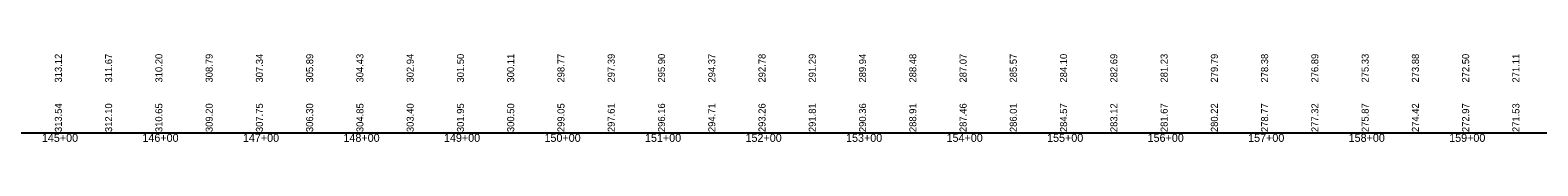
# Model space of a CAD drawing. Extents: x 1876258 to 1932803, y 754739 to 837911.
# Drawn here: x 1892831 to 1894330, y 830495 to 830583 of the extents above; entities that cross this region are included whole.
import ezdxf

# ---------------------------------------------------------------- set-up
doc = ezdxf.new("R2010")
doc.units = 0
for name, color, linetype in [('RD_DDB_StaTX', 7, 'Continuous'), ('RD_DDB_StripGrade', 7, 'Continuous'), ('RD_GPK_Profile_Cell', 7, 'Continuous')]:
    doc.layers.add(name, color=color, linetype=linetype)

msp = doc.modelspace()

# ---------------------------------------------------------------- linework, layer by layer
at = {"layer": 'RD_GPK_Profile_Cell'}
msp.add_line((1878363.1, 830504.3), (1926563.1, 830504.3), dxfattribs=at)

# ---------------------------------------------------------------- texts
at = {"layer": 'RD_DDB_StaTX'}
for s, p in [('145+00', (1892842.2, 830495.3)), ('145+00', (1892842.2, 830495.3)), ('146+00', (1892942.2, 830495.3)), ('146+00', (1892942.2, 830495.3)), ('147+00', (1893042.2, 830495.3)), ('147+00', (1893042.2, 830495.3)), ('148+00', (1893142.2, 830495.3)), ('148+00', (1893142.2, 830495.3)), ('149+00', (1893242.2, 830495.3)), ('149+00', (1893242.2, 830495.3)), ('150+00', (1893342.2, 830495.3)), ('150+00', (1893342.2, 830495.3)), ('151+00', (1893442.2, 830495.3)), ('151+00', (1893442.2, 830495.3)), ('152+00', (1893542.2, 830495.3)), ('152+00', (1893542.2, 830495.3)), ('153+00', (1893642.2, 830495.3)), ('153+00', (1893642.2, 830495.3)), ('154+00', (1893742.2, 830495.3)), ('154+00', (1893742.2, 830495.3)), ('155+00', (1893842.2, 830495.3)), ('155+00', (1893842.2, 830495.3)), ('156+00', (1893942.2, 830495.3)), ('156+00', (1893942.2, 830495.3)), ('157+00', (1894042.2, 830495.3)), ('157+00', (1894042.2, 830495.3)), ('158+00', (1894142.2, 830495.3)), ('158+00', (1894142.2, 830495.3)), ('159+00', (1894242.2, 830495.3)), ('159+00', (1894242.2, 830495.3))]:
    msp.add_text(s, height=8, dxfattribs=at).set_placement(p)
at = {"layer": 'RD_DDB_StripGrade'}
for s, p in [('313.12', (1892862.1, 830554.3)), ('311.67', (1892912.1, 830554.3)), ('310.20', (1892962.1, 830554.3)), ('308.79', (1893012.1, 830554.3)), ('307.34', (1893062.1, 830554.3)), ('305.89', (1893112.1, 830554.3)), ('304.43', (1893162.1, 830554.3)), ('302.94', (1893212.1, 830554.3)), ('301.50', (1893262.1, 830554.3)), ('300.11', (1893312.1, 830554.3)), ('298.77', (1893362.1, 830554.3)), ('297.39', (1893412.1, 830554.3)), ('295.90', (1893462.1, 830554.3)), ('294.37', (1893512.1, 830554.3)), ('292.78', (1893562.1, 830554.3)), ('291.29', (1893612.1, 830554.3)), ('289.94', (1893662.1, 830554.3)), ('288.48', (1893712.1, 830554.3)), ('287.07', (1893762.1, 830554.3)), ('285.57', (1893812.1, 830554.3)), ('284.10', (1893862.1, 830554.3)), ('282.69', (1893912.1, 830554.3)), ('281.23', (1893962.1, 830554.3)), ('279.79', (1894012.1, 830554.3)), ('278.38', (1894062.1, 830554.3)), ('276.89', (1894112.1, 830554.3)), ('275.33', (1894162.1, 830554.3)), ('273.88', (1894212.1, 830554.3)), ('272.50', (1894262.1, 830554.3)), ('271.11', (1894312.1, 830554.3)), ('313.54', (1892862.1, 830505)), ('312.10', (1892912.1, 830505)), ('310.65', (1892962.1, 830505)), ('309.20', (1893012.1, 830505)), ('307.75', (1893062.1, 830505)), ('306.30', (1893112.1, 830505)), ('304.85', (1893162.1, 830505)), ('303.40', (1893212.1, 830505)), ('301.95', (1893262.1, 830505)), ('300.50', (1893312.1, 830505)), ('299.05', (1893362.1, 830505)), ('297.61', (1893412.1, 830505)), ('296.16', (1893462.1, 830505)), ('294.71', (1893512.1, 830505)), ('293.26', (1893562.1, 830505)), ('291.81', (1893612.1, 830505)), ('290.36', (1893662.1, 830505)), ('288.91', (1893712.1, 830505)), ('287.46', (1893762.1, 830505)), ('286.01', (1893812.1, 830505)), ('284.57', (1893862.1, 830505)), ('283.12', (1893912.1, 830505)), ('281.67', (1893962.1, 830505)), ('280.22', (1894012.1, 830505)), ('278.77', (1894062.1, 830505)), ('277.32', (1894112.1, 830505)), ('275.87', (1894162.1, 830505)), ('274.42', (1894212.1, 830505)), ('272.97', (1894262.1, 830505)), ('271.53', (1894312.1, 830505))]:
    msp.add_text(s, height=7, rotation=90, dxfattribs=at).set_placement(p)

doc.saveas('drawing.dxf')
